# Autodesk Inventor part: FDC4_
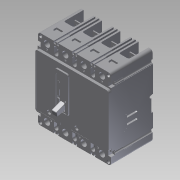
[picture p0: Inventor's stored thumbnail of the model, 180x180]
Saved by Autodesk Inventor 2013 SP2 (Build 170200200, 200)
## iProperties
Created: 2014-08
Part Number: FDC4_
Material: Generic
Document SubType Name: Modeling
Designer: DM/JS
Density: 1 g/cm^3
Description: TYPE FDC THERMAL MAGNETIC CIRCUIT BREAKERS FOUR POLE, SERIES C
Translation Standard: STEP AP214IS
FileName: Y:\ECO-062745\WIP\New\FD4_.stp
PreProcessor: Autodesk Inventor 2012
PostProcessor: Build: 219, Release: 2012 SP2 - Date: Fri 04/27/2012
Sent Units: inch
Uncertainty: 0.00039370078740199997
MXEDIT: false
MXINVTNRV: INV Versioned Component|FDC4_|003.0
Author: DM/JS
Revision Number: 003
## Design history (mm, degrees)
node "FDC4_"
node "L1"
node "L2"
node "L3"
node "L4"
node "T1"
node "T2"
node "T3"
node "T4"
body "Solid1"
node "Base1"
